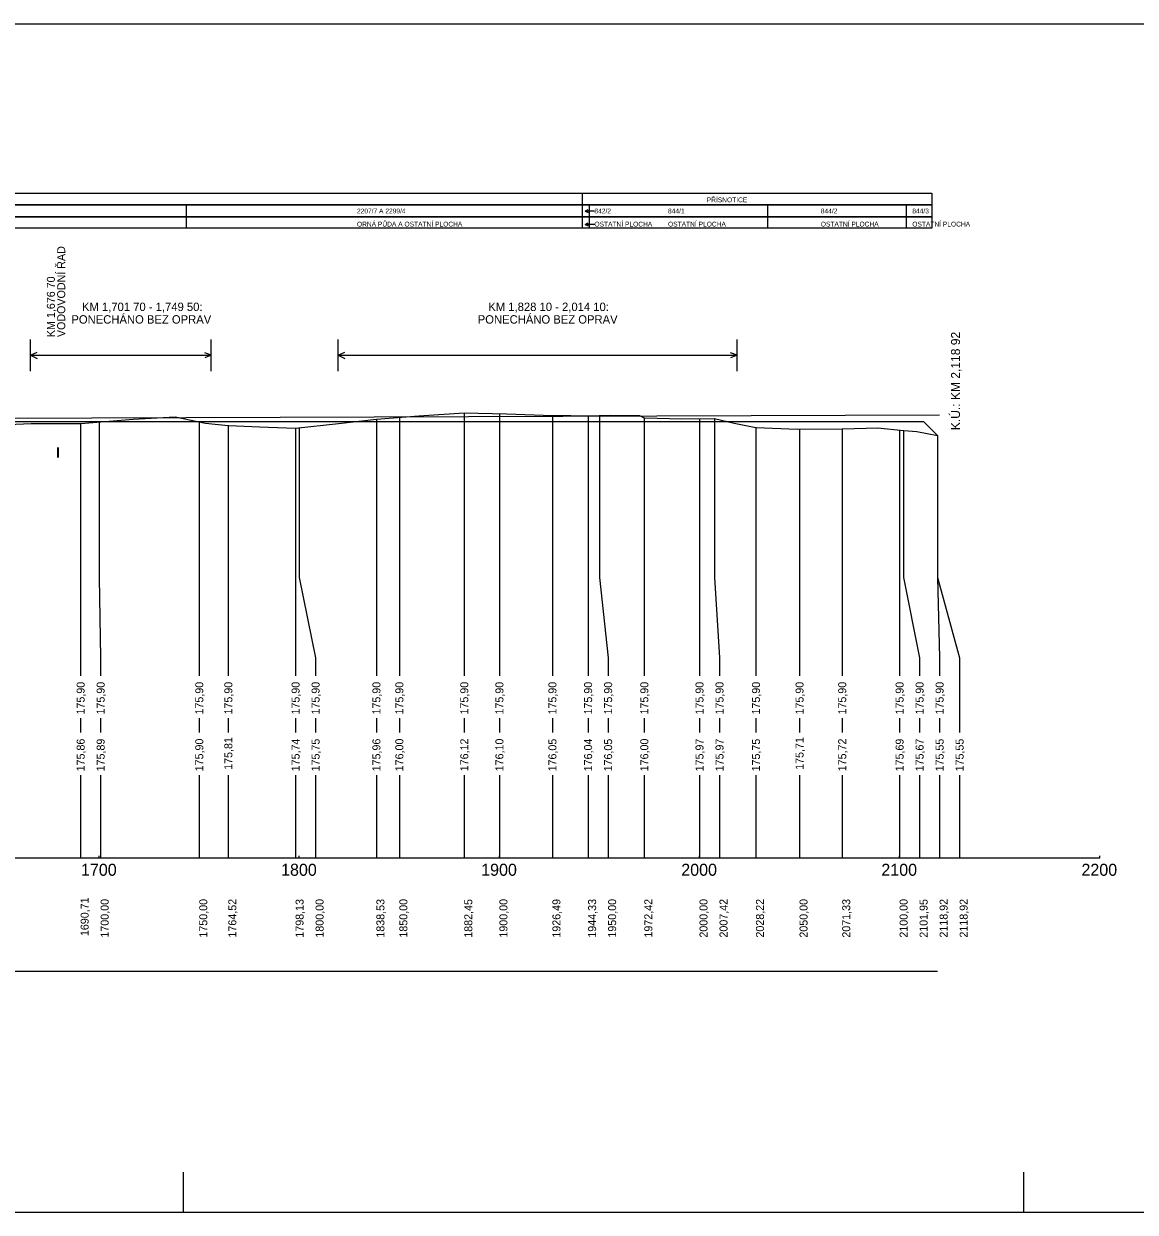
# Model space of a CAD drawing. Extents: x -614174 to -599765, y -1185887 to -1181080.
# Drawn here: x -611852 to -611297, y -1183382 to -1182788 of the extents above; entities that cross this region are included whole.
import ezdxf

# ---------------------------------------------------------------- set-up
doc = ezdxf.new("R2010")
doc.units = 0
for name, color, linetype in [('11', 7, 'Continuous'), ('13', 7, 'Continuous'), ('56', 7, 'Continuous'), ('Implicitní', 7, 'Continuous'), ('návrh', 7, 'Continuous')]:
    doc.layers.add(name, color=color, linetype=linetype)

msp = doc.modelspace()

# ---------------------------------------------------------------- linework, layer by layer
msp.add_line((-613514.51, -1182987.26), (-611402.58, -1182987.26))
for points in [[(-611871.77, -1182989.15), (-611848.49, -1182988.24), (-611823.8, -1182988.14), (-611823.69, -1182988.14), (-611797.58, -1182986.01), (-611776.61, -1182984.92), (-611761.41, -1182987.97), (-611749.99, -1182989.14), (-611749.79, -1182989.16), (-611734.41, -1182989.8), (-611716.38, -1182990.56), (-611716.35, -1182990.56), (-611694.93, -1182988.24), (-611675.98, -1182986.07), (-611675.86, -1182986.05), (-611654.71, -1182984.41), (-611632.14, -1182982.86), (-611632.06, -1182982.86), (-611610.99, -1182983.43), (-611588.02, -1182984.26), (-611588.01, -1182984.26), (-611578.77, -1182984.14), (-611570.18, -1182984.44), (-611570.07, -1182984.45), (-611559.22, -1182984.05), (-611544.5, -1182984.26), (-611542.09, -1182985.33), (-611541.84, -1182985.43), (-611523.41, -1182985.91), (-611507.12, -1182985.76), (-611507.09, -1182985.77), (-611497.11, -1182987.97), (-611486.29, -1182990.25), (-611486.26, -1182990.26), (-611465.64, -1182991.09), (-611443.18, -1182990.88), (-611443.06, -1182990.88), (-611425.34, -1182990.3), (-611412.55, -1182991.76), (-611412.37, -1182991.78), (-611405.87, -1182992.2), (-611395.59, -1182994.26), (-611395.58, -1182994.26)], [(-611675.98, -1182986.07), (-611675.98, -1183065.26), (-611675.98, -1183105.26), (-611675.98, -1183114.34)], [(-611664.51, -1182985.17), (-611664.51, -1183065.26), (-611664.51, -1183105.26), (-611664.51, -1183114.34)], [(-611632.06, -1182982.86), (-611632.06, -1183065.26), (-611632.06, -1183105.26), (-611632.06, -1183114.34)], [(-611614.51, -1182983.34), (-611614.51, -1183065.26), (-611614.51, -1183105.26), (-611614.51, -1183114.34)], [(-611588.02, -1182984.26), (-611588.02, -1183065.26), (-611588.02, -1183105.26), (-611588.02, -1183114.34)], [(-611570.18, -1182984.44), (-611570.18, -1183065.26), (-611570.18, -1183105.26), (-611570.18, -1183114.34)], [(-611564.51, -1182984.24), (-611564.51, -1183065.26), (-611560.18, -1183105.26), (-611560.18, -1183114.34)], [(-611542.09, -1182985.33), (-611542.09, -1183065.26), (-611542.09, -1183105.26), (-611542.09, -1183114.34)], [(-611514.51, -1182985.83), (-611514.51, -1183065.26), (-611514.51, -1183105.26), (-611514.51, -1183114.34)], [(-611507.09, -1182985.77), (-611507.09, -1183065.26), (-611504.51, -1183105.26), (-611504.51, -1183114.34)], [(-611823.8, -1182988.14), (-611823.8, -1183065.26), (-611823.8, -1183105.26), (-611823.8, -1183114.34)], [(-611814.51, -1182987.39), (-611814.51, -1183065.26), (-611813.8, -1183105.26), (-611813.8, -1183114.34)], [(-611764.51, -1182987.35), (-611764.51, -1183065.26), (-611764.51, -1183105.26), (-611764.51, -1183114.34)], [(-611749.99, -1182989.14), (-611749.99, -1183065.26), (-611749.99, -1183105.26), (-611749.99, -1183114.34)], [(-611716.38, -1182990.56), (-611716.38, -1183065.26), (-611716.38, -1183105.26), (-611716.38, -1183114.34)], [(-611714.51, -1182990.36), (-611714.51, -1183065.26), (-611706.38, -1183105.26), (-611706.38, -1183114.34)], [(-611486.29, -1182990.25), (-611486.29, -1183065.26), (-611486.29, -1183105.26), (-611486.29, -1183114.34)], [(-611464.51, -1182991.08), (-611464.51, -1183065.26), (-611464.51, -1183105.26), (-611464.51, -1183114.34)], [(-611443.18, -1182990.88), (-611443.18, -1183065.26), (-611443.18, -1183105.26), (-611443.18, -1183114.34)], [(-611414.51, -1182991.54), (-611414.51, -1183065.26), (-611414.51, -1183105.26), (-611414.51, -1183114.34)], [(-611412.55, -1182991.76), (-611412.55, -1183065.26), (-611404.51, -1183105.26), (-611404.51, -1183114.34)], [(-611395.59, -1182994.26), (-611395.59, -1183065.26), (-611394.51, -1183105.26), (-611394.51, -1183114.34)], [(-611395.58, -1182994.26), (-611395.58, -1183065.26), (-611384.51, -1183105.26), (-611384.51, -1183142.7)], [(-611823.8, -1183135.54), (-611823.8, -1183142.7)], [(-611813.8, -1183135.54), (-611813.8, -1183142.7)], [(-611764.51, -1183135.54), (-611764.51, -1183142.7)], [(-611749.99, -1183135.54), (-611749.99, -1183142.7)], [(-611716.38, -1183135.54), (-611716.38, -1183142.7)], [(-611706.38, -1183135.54), (-611706.38, -1183142.7)], [(-611675.98, -1183135.54), (-611675.98, -1183142.7)], [(-611664.51, -1183135.54), (-611664.51, -1183142.7)], [(-611632.06, -1183135.54), (-611632.06, -1183142.7)], [(-611614.51, -1183135.54), (-611614.51, -1183142.7)], [(-611588.02, -1183135.54), (-611588.02, -1183142.7)], [(-611570.18, -1183135.54), (-611570.18, -1183142.7)], [(-611560.18, -1183135.54), (-611560.18, -1183142.7)], [(-611542.09, -1183135.54), (-611542.09, -1183142.7)], [(-611514.51, -1183135.54), (-611514.51, -1183142.7)], [(-611504.51, -1183135.54), (-611504.51, -1183142.7)], [(-611486.29, -1183135.54), (-611486.29, -1183142.7)], [(-611464.51, -1183135.54), (-611464.51, -1183142.7)], [(-611443.18, -1183135.54), (-611443.18, -1183142.7)], [(-611414.51, -1183135.54), (-611414.51, -1183142.7)], [(-611404.51, -1183135.54), (-611404.51, -1183142.7)], [(-611394.51, -1183135.54), (-611394.51, -1183142.7)], [(-611823.8, -1183163.91), (-611823.8, -1183205.26)], [(-611813.8, -1183163.91), (-611813.8, -1183205.26)], [(-611764.51, -1183163.91), (-611764.51, -1183205.26)], [(-611749.99, -1183163.91), (-611749.99, -1183205.26)], [(-611716.38, -1183163.91), (-611716.38, -1183205.26)], [(-611706.38, -1183163.91), (-611706.38, -1183205.26)], [(-611675.98, -1183163.91), (-611675.98, -1183205.26)], [(-611664.51, -1183163.91), (-611664.51, -1183205.26)], [(-611632.06, -1183163.91), (-611632.06, -1183205.26)], [(-611614.51, -1183163.91), (-611614.51, -1183205.26)], [(-611588.02, -1183163.91), (-611588.02, -1183205.26)], [(-611570.18, -1183163.91), (-611570.18, -1183205.26)], [(-611560.18, -1183163.91), (-611560.18, -1183205.26)], [(-611542.09, -1183163.91), (-611542.09, -1183205.26)], [(-611514.51, -1183163.91), (-611514.51, -1183205.26)], [(-611504.51, -1183163.91), (-611504.51, -1183205.26)], [(-611486.29, -1183163.91), (-611486.29, -1183205.26)], [(-611464.51, -1183163.91), (-611464.51, -1183205.26)], [(-611443.18, -1183163.91), (-611443.18, -1183205.26)], [(-611414.51, -1183163.91), (-611414.51, -1183205.26)], [(-611404.51, -1183163.91), (-611404.51, -1183205.26)], [(-611394.51, -1183163.91), (-611394.51, -1183205.26)], [(-611384.51, -1183163.91), (-611384.51, -1183205.26)], [(-613514.51, -1183261.99), (-611395.59, -1183261.99)]]:
    msp.add_lwpolyline(points)
at = {"layer": '56'}
for p, q in [((-613514.51, -1183205.26), (-611314.51, -1183205.26)), ((-611814.51, -1183205.26), (-611814.51, -1183204.26)), ((-611714.51, -1183205.26), (-611714.51, -1183204.26)), ((-611614.51, -1183205.26), (-611614.51, -1183204.26)), ((-611514.51, -1183205.26), (-611514.51, -1183204.26)), ((-611414.51, -1183205.26), (-611414.51, -1183204.26)), ((-611314.51, -1183205.26), (-611314.51, -1183204.26)), ((-611314.51, -1183205.26), (-611314.51, -1183204.26))]:
    msp.add_line(p, q, dxfattribs=at)
at = {"layer": 'návrh'}
for p, q in [((-613657.4, -1182788.43), (-610932.51, -1182788.43)), ((-611573.11, -1182873.17), (-611573.11, -1182890.67)), ((-611771.11, -1182879), (-611771.11, -1182890.67)), ((-611569.71, -1182879), (-611569.71, -1182890.67)), ((-611480.51, -1182879), (-611480.51, -1182890.67)), ((-611411.3, -1182879), (-611411.3, -1182890.67)), ((-611571.71, -1182882.01), (-611570.17, -1182881.27)), ((-611567.03, -1182882.01), (-611571.71, -1182882.01)), ((-611571.71, -1182882.01), (-611570.17, -1182882.75)), ((-611571.71, -1182888.71), (-611570.17, -1182887.97)), ((-611567.03, -1182888.71), (-611571.71, -1182888.71)), ((-611571.71, -1182888.71), (-611570.17, -1182889.45)), ((-611848.93, -1182961.98), (-611848.93, -1182946.2)), ((-611758.61, -1182961.98), (-611758.61, -1182946.2)), ((-611695.12, -1182961.98), (-611695.12, -1182946.2)), ((-611495.76, -1182961.98), (-611495.76, -1182946.2)), ((-611848.93, -1182954.09), (-611845.56, -1182952.64)), ((-611848.93, -1182954.09), (-611845.53, -1182955.65)), ((-611848.93, -1182954.09), (-611758.61, -1182954.09)), ((-611758.61, -1182954.09), (-611761.79, -1182952.85)), ((-611758.61, -1182954.09), (-611761.79, -1182955.45)), ((-611695.12, -1182954.09), (-611691.75, -1182952.64)), ((-611695.12, -1182954.09), (-611691.71, -1182955.65)), ((-611695.12, -1182954.09), (-611495.76, -1182954.09)), ((-611495.76, -1182954.09), (-611498.94, -1182952.85)), ((-611495.76, -1182954.09), (-611498.94, -1182955.45)), ((-611394.51, -1182984.06), (-613514.51, -1182991.66)), ((-611395.58, -1182994.26), (-611402.58, -1182987.26)), ((-611772.51, -1183362.43), (-611772.51, -1183382.43)), ((-611352.51, -1183362.43), (-611352.51, -1183382.43)), ((-613452.51, -1183382.43), (-610932.51, -1183382.43))]:
    msp.add_line(p, q, dxfattribs=at)
for points in [[(-613514.51, -1182873.17), (-611398.36, -1182873.17), (-611398.36, -1182879), (-613514.51, -1182879)], [(-613514.51, -1182879), (-611398.36, -1182879), (-611398.36, -1182884.84), (-613514.51, -1182884.84)], [(-613514.51, -1182884.84), (-611398.36, -1182884.84), (-611398.36, -1182890.67), (-613514.51, -1182890.67)]]:
    msp.add_lwpolyline(points, close=True, dxfattribs=at)
msp.add_ellipse((-611835.11, -1183002.74), major_axis=(0, 2.5), ratio=0.05, dxfattribs=at)

# ---------------------------------------------------------------- texts
at = {"layer": '11'}
for s, p in [('175,90', (-611821.8, -1183133.67)), ('175,90', (-611811.8, -1183133.67)), ('175,90', (-611762.51, -1183133.67)), ('175,90', (-611747.99, -1183133.67)), ('175,90', (-611714.38, -1183133.67)), ('175,90', (-611704.38, -1183133.67)), ('175,90', (-611673.98, -1183133.67)), ('175,90', (-611662.51, -1183133.67)), ('175,90', (-611630.06, -1183133.67)), ('175,90', (-611612.51, -1183133.67)), ('175,90', (-611586.02, -1183133.67)), ('175,90', (-611568.18, -1183133.67)), ('175,90', (-611558.18, -1183133.67)), ('175,90', (-611540.09, -1183133.67)), ('175,90', (-611512.51, -1183133.67)), ('175,90', (-611502.51, -1183133.67)), ('175,90', (-611484.29, -1183133.67)), ('175,90', (-611462.51, -1183133.67)), ('175,90', (-611441.18, -1183133.67)), ('175,90', (-611412.51, -1183133.67)), ('175,90', (-611402.51, -1183133.67)), ('175,90', (-611392.51, -1183133.67)), ('175,86', (-611821.8, -1183162.09)), ('175,89', (-611811.8, -1183162.1)), ('175,90', (-611762.51, -1183162.07)), ('175,81', (-611747.99, -1183161.32)), ('175,74', (-611714.38, -1183162.07)), ('175,75', (-611704.38, -1183162.12)), ('175,96', (-611673.98, -1183162.09)), ('176,00', (-611662.51, -1183162.07)), ('176,12', (-611630.06, -1183162.05)), ('176,10', (-611612.51, -1183162.07)), ('176,05', (-611586.02, -1183162.12)), ('176,04', (-611568.18, -1183162.07)), ('176,05', (-611558.18, -1183162.12)), ('176,00', (-611540.09, -1183162.07)), ('175,97', (-611512.51, -1183162.09)), ('175,97', (-611502.51, -1183162.09)), ('175,75', (-611484.29, -1183162.12)), ('175,71', (-611462.51, -1183161.32)), ('175,72', (-611441.18, -1183162.05)), ('175,69', (-611412.51, -1183162.1)), ('175,67', (-611402.51, -1183162.09)), ('175,55', (-611392.51, -1183162.12)), ('175,55', (-611382.51, -1183162.12)), ('1690,71', (-611819.8, -1183244.42)), ('1700,00', (-611809.8, -1183245.18)), ('1750,00', (-611760.51, -1183245.18)), ('1764,52', (-611745.99, -1183245.15)), ('1798,13', (-611712.38, -1183245.2)), ('1800,00', (-611702.38, -1183245.18)), ('1838,53', (-611671.98, -1183245.2)), ('1850,00', (-611660.51, -1183245.18)), ('1882,45', (-611628.06, -1183245.23)), ('1900,00', (-611610.51, -1183245.18)), ('1926,49', (-611584.02, -1183245.2)), ('1944,33', (-611566.18, -1183245.2)), ('1950,00', (-611556.18, -1183245.18)), ('1972,42', (-611538.09, -1183245.15)), ('2000,00', (-611510.51, -1183245.18)), ('2007,42', (-611500.51, -1183245.15)), ('2028,22', (-611482.29, -1183245.15)), ('2050,00', (-611460.51, -1183245.18)), ('2071,33', (-611439.18, -1183245.2)), ('2100,00', (-611410.51, -1183245.18)), ('2101,95', (-611400.51, -1183245.23)), ('2118,92', (-611390.51, -1183245.15)), ('2118,92', (-611380.51, -1183245.15))]:
    msp.add_text(s, height=4, rotation=90, dxfattribs=at).set_placement(p)
at = {"layer": '13'}
for s, height, p in [('PŘÍSNOTICE', 2.4, (-611510.88, -1182877.64)), ('2207/7 A 2299/4', 2.4, (-611685.71, -1182883.21)), ('842/2', 2.4, (-611567.03, -1182883.21)), ('844/1', 2.4, (-611530.24, -1182883.21)), ('844/2', 2.4, (-611453.88, -1182883.21)), ('844/3', 2.4, (-611408.16, -1182883.21)), ('ORNÁ PŮDA A OSTATNÍ PLOCHA', 2.4, (-611685.71, -1182889.76)), ('OSTATNÍ PLOCHA', 2.4, (-611567.03, -1182889.76)), ('OSTATNÍ PLOCHA', 2.4, (-611530.24, -1182889.76)), ('OSTATNÍ PLOCHA', 2.4, (-611453.88, -1182889.76)), ('OSTATNÍ PLOCHA', 2.4, (-611408.16, -1182889.76)), ('PONECHÁNO BEZ OPRAV', 4.2, (-611828.43, -1182938.3)), ('KM 1,701 70 - 1,749 50: ', 4.2, (-611823.14, -1182932)), ('PONECHÁNO BEZ OPRAV', 4.2, (-611625.34, -1182938.3)), ('KM 1,828 10 - 2,014 10: ', 4.2, (-611620.05, -1182932)), ('1700', 6, (-611823.63, -1183214.26)), ('1800', 6, (-611723.63, -1183214.26)), ('1900', 6, (-611623.63, -1183214.26)), ('2000', 6, (-611523.63, -1183214.26)), ('2100', 6, (-611423.63, -1183214.26)), ('2200', 6, (-611323.63, -1183214.26))]:
    msp.add_text(s, height=height, dxfattribs=at).set_placement(p)
msp.add_text('K.Ú.: KM 2,118 92 ', height=4.5, rotation=90, dxfattribs=at).set_placement((-611384.31, -1182991.56))
at = {"layer": 'Implicitní'}
for s, p in [('VODOVODNÍ ŘAD ', (-611831.51, -1182945.04)), ('KM 1,676 70  ', (-611836.68, -1182945.04))]:
    msp.add_text(s, height=4, rotation=90, dxfattribs=at).set_placement(p)

doc.saveas('drawing.dxf')
